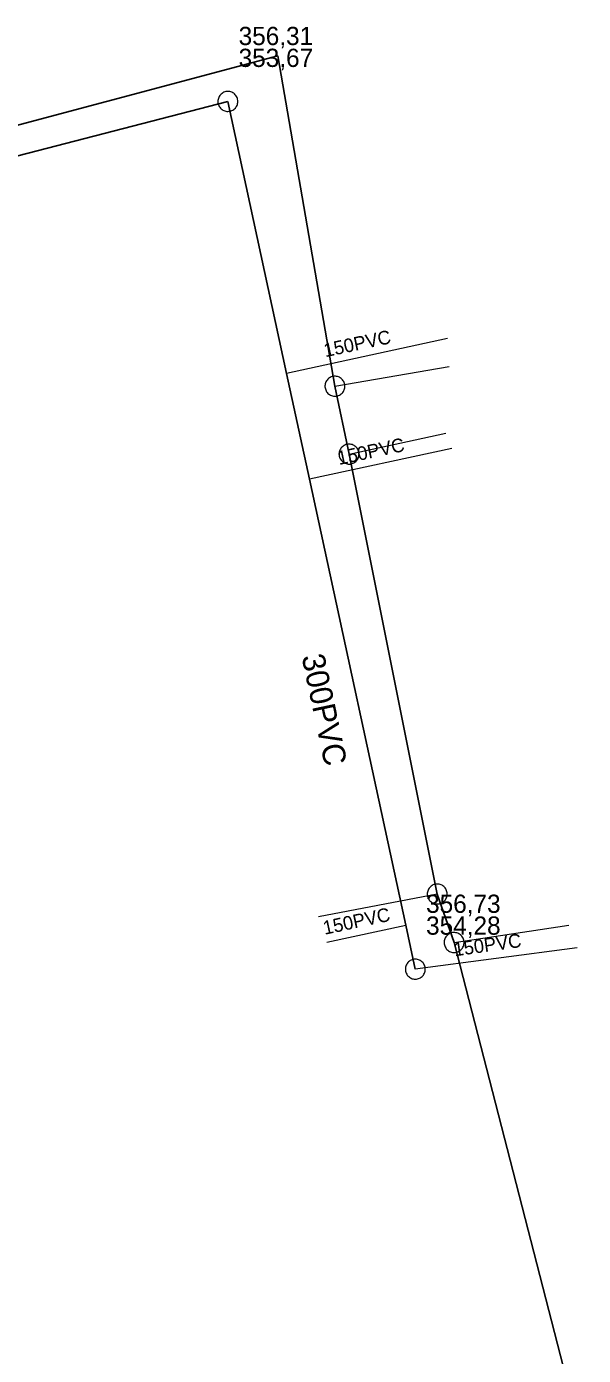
# Model space of a CAD drawing. Extents: x -741806 to -738704, y -1059275 to -1055387.
# Drawn here: x -740624.2 to -740599.8, y -1057256 to -1057197.7 of the extents above; entities that cross this region are included whole.
import ezdxf

# ---------------------------------------------------------------- set-up
doc = ezdxf.new("R2010")
doc.units = 0
doc.header["$LTSCALE"] = 0.4
for name, color, linetype, lineweight in [('2', 7, 'Continuous', 25), ('21', 7, 'Continuous', 13), ('3', 7, 'Continuous', 13), ('51', 7, 'Continuous', 13), ('52', 7, 'Continuous', 25), ('56', 7, 'Continuous', 13), ('6', 7, 'Continuous', 13)]:
    doc.layers.add(name, color=color, linetype=linetype, lineweight=lineweight)
doc.layers.add('5', color=7, linetype='Continuous')
doc.layers.add('55', color=7, linetype='Continuous')

msp = doc.modelspace()

# ---------------------------------------------------------------- linework, layer by layer
at = {"layer": '2'}
for points in [[(-740615.399, -1057200.96), (-740634.256, -1057205.84), (-740653.813, -1057210.902), (-740659.397, -1057212.347), (-740663.62, -1057213.44)], [(-740607.17, -1057239.05), (-740607.589, -1057237.11), (-740611.818, -1057217.54), (-740612.82, -1057212.896), (-740615.399, -1057200.96)]]:
    msp.add_lwpolyline(points, dxfattribs=at)
at = {"layer": '21'}
for p, q in [((-740610.699, -1057213.46), (-740605.68, -1057212.6)), ((-740610.079, -1057216.44), (-740605.829, -1057215.52)), ((-740606.21, -1057235.75), (-740611.42, -1057236.75)), ((-740605.469, -1057237.879), (-740600.43, -1057237.11))]:
    msp.add_line(p, q, dxfattribs=at)
at = {"layer": '3'}
msp.add_lwpolyline([(-740615.491, -1057200.531), (-740615.534, -1057200.544), (-740615.576, -1057200.56), (-740615.618, -1057200.581), (-740615.655, -1057200.606), (-740615.691, -1057200.635), (-740615.724, -1057200.668), (-740615.752, -1057200.703), (-740615.778, -1057200.742), (-740615.797, -1057200.783), (-740615.814, -1057200.825), (-740615.826, -1057200.87), (-740615.833, -1057200.915), (-740615.835, -1057200.961), (-740615.833, -1057201.006), (-740615.825, -1057201.052), (-740615.813, -1057201.096), (-740615.796, -1057201.139), (-740615.776, -1057201.179), (-740615.75, -1057201.218), (-740615.721, -1057201.253), (-740615.689, -1057201.285), (-740615.654, -1057201.313), (-740615.615, -1057201.339), (-740615.574, -1057201.36), (-740615.531, -1057201.376), (-740615.487, -1057201.387), (-740615.442, -1057201.395), (-740615.396, -1057201.397), (-740615.35, -1057201.394), (-740615.305, -1057201.386), (-740615.261, -1057201.375), (-740615.219, -1057201.359), (-740615.177, -1057201.337), (-740615.139, -1057201.312), (-740615.104, -1057201.284), (-740615.071, -1057201.251), (-740615.043, -1057201.215), (-740615.018, -1057201.176), (-740614.998, -1057201.136), (-740614.981, -1057201.093), (-740614.969, -1057201.049), (-740614.962, -1057201.003), (-740614.959, -1057200.958), (-740614.962, -1057200.912), (-740614.97, -1057200.867), (-740614.982, -1057200.822), (-740614.998, -1057200.78), (-740615.019, -1057200.739), (-740615.045, -1057200.701), (-740615.074, -1057200.665), (-740615.106, -1057200.633), (-740615.141, -1057200.604), (-740615.18, -1057200.58), (-740615.221, -1057200.559), (-740615.264, -1057200.543), (-740615.309, -1057200.531), (-740615.353, -1057200.524), (-740615.399, -1057200.522), (-740615.445, -1057200.524), (-740615.49, -1057200.531)], dxfattribs=at)
msp.add_lwpolyline([(-740607.261, -1057238.621), (-740607.305, -1057238.634), (-740607.347, -1057238.65), (-740607.389, -1057238.671), (-740607.426, -1057238.696), (-740607.462, -1057238.725), (-740607.495, -1057238.758), (-740607.523, -1057238.793), (-740607.549, -1057238.832), (-740607.568, -1057238.873), (-740607.585, -1057238.915), (-740607.597, -1057238.96), (-740607.604, -1057239.005), (-740607.606, -1057239.051), (-740607.604, -1057239.096), (-740607.596, -1057239.142), (-740607.584, -1057239.186), (-740607.567, -1057239.228), (-740607.547, -1057239.269), (-740607.521, -1057239.308), (-740607.492, -1057239.343), (-740607.46, -1057239.375), (-740607.425, -1057239.403), (-740607.386, -1057239.429), (-740607.345, -1057239.45), (-740607.302, -1057239.466), (-740607.258, -1057239.477), (-740607.213, -1057239.485), (-740607.167, -1057239.487), (-740607.121, -1057239.484), (-740607.076, -1057239.476), (-740607.032, -1057239.465), (-740606.99, -1057239.449), (-740606.948, -1057239.427), (-740606.91, -1057239.402), (-740606.875, -1057239.374), (-740606.842, -1057239.341), (-740606.814, -1057239.305), (-740606.789, -1057239.266), (-740606.769, -1057239.226), (-740606.752, -1057239.183), (-740606.74, -1057239.139), (-740606.733, -1057239.093), (-740606.73, -1057239.048), (-740606.733, -1057239.002), (-740606.741, -1057238.957), (-740606.753, -1057238.912), (-740606.769, -1057238.87), (-740606.79, -1057238.829), (-740606.816, -1057238.791), (-740606.845, -1057238.755), (-740606.877, -1057238.723), (-740606.912, -1057238.694), (-740606.951, -1057238.67), (-740606.992, -1057238.649), (-740607.035, -1057238.633), (-740607.079, -1057238.621), (-740607.124, -1057238.614), (-740607.17, -1057238.612), (-740607.216, -1057238.614)], close=True, dxfattribs=at)
at = {"layer": '51'}
for points in [[(-740610.268, -1057213.386), (-740610.277, -1057213.342), (-740610.292, -1057213.299), (-740610.311, -1057213.257), (-740610.334, -1057213.218), (-740610.362, -1057213.181), (-740610.393, -1057213.147), (-740610.427, -1057213.117), (-740610.465, -1057213.09), (-740610.505, -1057213.069), (-740610.546, -1057213.05), (-740610.59, -1057213.037), (-740610.636, -1057213.027), (-740610.681, -1057213.023), (-740610.727, -1057213.023), (-740610.772, -1057213.029), (-740610.817, -1057213.039), (-740610.86, -1057213.054), (-740610.902, -1057213.073), (-740610.941, -1057213.097), (-740610.978, -1057213.124), (-740611.011, -1057213.155), (-740611.042, -1057213.189), (-740611.068, -1057213.227), (-740611.091, -1057213.266), (-740611.109, -1057213.309), (-740611.123, -1057213.353), (-740611.131, -1057213.397), (-740611.135, -1057213.444), (-740611.135, -1057213.489), (-740611.13, -1057213.535), (-740611.119, -1057213.579), (-740611.105, -1057213.622), (-740611.085, -1057213.664), (-740611.063, -1057213.703), (-740611.035, -1057213.74), (-740611.004, -1057213.774), (-740610.969, -1057213.804), (-740610.932, -1057213.831), (-740610.892, -1057213.852), (-740610.85, -1057213.871), (-740610.806, -1057213.884), (-740610.761, -1057213.894), (-740610.716, -1057213.897), (-740610.67, -1057213.897), (-740610.624, -1057213.892), (-740610.579, -1057213.882), (-740610.536, -1057213.866), (-740610.495, -1057213.848), (-740610.455, -1057213.824), (-740610.419, -1057213.797), (-740610.385, -1057213.766), (-740610.355, -1057213.732), (-740610.329, -1057213.694), (-740610.306, -1057213.655), (-740610.288, -1057213.612), (-740610.274, -1057213.568), (-740610.265, -1057213.524), (-740610.261, -1057213.477), (-740610.262, -1057213.432), (-740610.268, -1057213.387)], [(-740609.651, -1057216.348), (-740609.663, -1057216.304), (-740609.679, -1057216.261), (-740609.7, -1057216.22), (-740609.725, -1057216.182), (-740609.754, -1057216.147), (-740609.787, -1057216.114), (-740609.823, -1057216.086), (-740609.861, -1057216.06), (-740609.902, -1057216.041), (-740609.944, -1057216.024), (-740609.989, -1057216.012), (-740610.034, -1057216.005), (-740610.08, -1057216.002), (-740610.125, -1057216.005), (-740610.171, -1057216.013), (-740610.215, -1057216.025), (-740610.258, -1057216.041), (-740610.298, -1057216.062), (-740610.337, -1057216.088), (-740610.372, -1057216.117), (-740610.404, -1057216.149), (-740610.434, -1057216.184), (-740610.458, -1057216.223), (-740610.479, -1057216.264), (-740610.495, -1057216.307), (-740610.507, -1057216.352), (-740610.514, -1057216.396), (-740610.516, -1057216.443), (-740610.513, -1057216.488), (-740610.506, -1057216.534), (-740610.494, -1057216.577), (-740610.477, -1057216.619), (-740610.456, -1057216.661), (-740610.432, -1057216.699), (-740610.402, -1057216.734), (-740610.37, -1057216.767), (-740610.334, -1057216.795), (-740610.296, -1057216.821), (-740610.255, -1057216.84), (-740610.212, -1057216.857), (-740610.168, -1057216.869), (-740610.122, -1057216.876), (-740610.077, -1057216.878), (-740610.031, -1057216.876), (-740609.986, -1057216.868), (-740609.941, -1057216.856), (-740609.899, -1057216.839), (-740609.858, -1057216.819), (-740609.82, -1057216.793), (-740609.784, -1057216.764), (-740609.752, -1057216.732), (-740609.723, -1057216.697), (-740609.699, -1057216.658), (-740609.678, -1057216.617), (-740609.662, -1057216.574), (-740609.65, -1057216.529), (-740609.643, -1057216.485), (-740609.641, -1057216.438), (-740609.644, -1057216.393), (-740609.651, -1057216.349)], [(-740606.352, -1057235.337), (-740606.394, -1057235.353), (-740606.435, -1057235.375), (-740606.473, -1057235.401), (-740606.507, -1057235.43), (-740606.539, -1057235.463), (-740606.568, -1057235.499), (-740606.592, -1057235.538), (-740606.612, -1057235.579), (-740606.627, -1057235.622), (-740606.638, -1057235.667), (-740606.644, -1057235.712), (-740606.646, -1057235.758), (-740606.643, -1057235.804), (-740606.635, -1057235.849), (-740606.622, -1057235.893), (-740606.605, -1057235.936), (-740606.583, -1057235.976), (-740606.558, -1057236.013), (-740606.528, -1057236.048), (-740606.494, -1057236.08), (-740606.458, -1057236.108), (-740606.42, -1057236.133), (-740606.378, -1057236.152), (-740606.336, -1057236.168), (-740606.291, -1057236.179), (-740606.245, -1057236.185), (-740606.2, -1057236.187), (-740606.154, -1057236.183), (-740606.109, -1057236.175), (-740606.064, -1057236.163), (-740606.023, -1057236.145), (-740605.983, -1057236.124), (-740605.944, -1057236.098), (-740605.91, -1057236.069), (-740605.878, -1057236.035), (-740605.849, -1057235.999), (-740605.826, -1057235.96), (-740605.805, -1057235.919), (-740605.79, -1057235.876), (-740605.779, -1057235.832), (-740605.773, -1057235.786), (-740605.771, -1057235.74), (-740605.775, -1057235.695), (-740605.782, -1057235.65), (-740605.795, -1057235.606), (-740605.812, -1057235.563), (-740605.835, -1057235.523), (-740605.859, -1057235.485), (-740605.89, -1057235.45), (-740605.923, -1057235.418), (-740605.959, -1057235.39), (-740605.997, -1057235.366), (-740606.039, -1057235.346), (-740606.081, -1057235.33), (-740606.127, -1057235.319), (-740606.172, -1057235.313), (-740606.217, -1057235.312), (-740606.264, -1057235.315), (-740606.308, -1057235.323), (-740606.351, -1057235.336)], [(-740605.577, -1057237.455), (-740605.62, -1057237.468), (-740605.662, -1057237.486), (-740605.702, -1057237.509), (-740605.739, -1057237.535), (-740605.774, -1057237.566), (-740605.805, -1057237.6), (-740605.832, -1057237.636), (-740605.856, -1057237.676), (-740605.874, -1057237.718), (-740605.889, -1057237.761), (-740605.899, -1057237.805), (-740605.905, -1057237.851), (-740605.905, -1057237.897), (-740605.901, -1057237.942), (-740605.891, -1057237.987), (-740605.878, -1057238.031), (-740605.86, -1057238.073), (-740605.837, -1057238.113), (-740605.81, -1057238.15), (-740605.779, -1057238.185), (-740605.746, -1057238.215), (-740605.71, -1057238.243), (-740605.67, -1057238.266), (-740605.629, -1057238.285), (-740605.585, -1057238.3), (-740605.54, -1057238.31), (-740605.495, -1057238.315), (-740605.448, -1057238.315), (-740605.403, -1057238.311), (-740605.358, -1057238.302), (-740605.315, -1057238.288), (-740605.273, -1057238.27), (-740605.233, -1057238.247), (-740605.196, -1057238.221), (-740605.161, -1057238.191), (-740605.13, -1057238.157), (-740605.103, -1057238.12), (-740605.079, -1057238.081), (-740605.061, -1057238.039), (-740605.046, -1057237.996), (-740605.036, -1057237.951), (-740605.031, -1057237.905), (-740605.031, -1057237.86), (-740605.034, -1057237.814), (-740605.044, -1057237.769), (-740605.057, -1057237.725), (-740605.076, -1057237.684), (-740605.098, -1057237.644), (-740605.125, -1057237.606), (-740605.156, -1057237.572), (-740605.189, -1057237.541), (-740605.225, -1057237.513), (-740605.265, -1057237.491), (-740605.306, -1057237.471), (-740605.35, -1057237.457), (-740605.395, -1057237.447), (-740605.44, -1057237.442), (-740605.487, -1057237.441), (-740605.532, -1057237.446), (-740605.576, -1057237.455)]]:
    msp.add_lwpolyline(points, dxfattribs=at)
at = {"layer": '52'}
msp.add_lwpolyline([(-740599.789, -1057271.49), (-740600.43, -1057271.03), (-740601.149, -1057264.71), (-740599.89, -1057259.55), (-740605.469, -1057237.879), (-740606.21, -1057235.75), (-740610.079, -1057216.44), (-740610.699, -1057213.46), (-740613.21, -1057198.96), (-740635.57, -1057204.919), (-740654.67, -1057209.71), (-740658.96, -1057210.78), (-740671.342, -1057213.918), (-740678.14, -1057215.639), (-740680.199, -1057216.11)], dxfattribs=at)
at = {"layer": '56'}
for p, q in [((-740605.76, -1057211.37), (-740612.82, -1057212.896)), ((-740605.57, -1057216.19), (-740611.818, -1057217.54)), ((-740611.059, -1057237.86), (-740607.589, -1057237.11)), ((-740600.059, -1057238.11), (-740607.17, -1057239.05))]:
    msp.add_line(p, q, dxfattribs=at)

# ---------------------------------------------------------------- texts
at = {"layer": '5'}
msp.add_text('300PVC', height=1, rotation=282, dxfattribs=at).set_placement((-740612.167, -1057225.323))
at = {"layer": '55'}
for rotation, p in [(12, (-740611.119, -1057212.189)), (12, (-740610.523, -1057216.921)), (12, (-740611.153, -1057237.541)), (8, (-740605.442, -1057238.487))]:
    msp.add_text('150PVC', height=0.6, rotation=rotation, dxfattribs=at).set_placement(p)
at = {"layer": '6'}
for s, p in [('356,31', (-740614.927, -1057198.486)), ('353,67', (-740614.927, -1057199.446)), ('356,73', (-740606.697, -1057236.576)), ('354,28', (-740606.697, -1057237.536))]:
    msp.add_text(s, height=0.8, dxfattribs=at).set_placement(p)

doc.saveas('drawing.dxf')
